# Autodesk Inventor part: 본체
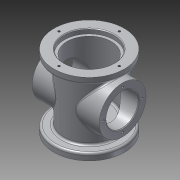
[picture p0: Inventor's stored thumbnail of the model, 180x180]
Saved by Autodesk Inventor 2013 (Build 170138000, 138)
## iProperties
Created: 2018-02
Part Number: 본체
Material: 알루미늄 6061
Document SubType Name: Modeling
Designer: Administrator
Density: 2.71 g/cm^3
Mass: 771.854 g
Surface Area: 821.824 cm^2
Volume: 284.817 cm^3
Author: Administrator
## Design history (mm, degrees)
sketch "스케치1"
  geometry: C1 r 38 at (0, 0); 1 further point
  constraints: 1 centre point, 1 coincident
  dimensions: "d0" = 76 diameter of C1
extrude "돌출1" new body sketch "스케치1" stored distance "d2" = 88; taper "d3" = 0 deg
sketch "스케치2"
  geometry: C1 r 38 at (0, 0) reference; C2 r 52.5 at (0, 0)
  constraints: 1 centre point, 1 coincident
  dimensions: "d5" = 105 diameter of C2
extrude "돌출2" join sketch "스케치2" distance "d7" = 10; taper "d8" = 0 deg
hole "구멍1" diameter "d11" = 66; stored, may be unused: countersink angle "d15" = 90 deg, drill point angle "d17" = 0 deg; dims "d9" = 10, "d10" = 10, "d12" = 6, "d13" = 74, "d14" = 7, "d16" = 86
hole "구멍2" diameter "d20" = 10; stored, may be unused: countersink angle "d24" = 90 deg, drill point angle "d26" = 0 deg; dims "d18" = 10, "d19" = 10, "d21" = 6, "d22" = 68, "d23" = 16, "d25" = 22
node "작업 평면1"
sketch "스케치3"
  geometry: C1 r 35 at (0, 0); 1 further point
  constraints: 1 centre point, 1 coincident
  dimensions: "d29" = 70 diameter of C1
extrude "돌출3" join sketch "스케치3" stored distance "d31" = 10; taper "d32" = 0 deg
hole "구멍3" diameter "d35" = 48; stored, may be unused: countersink angle "d39" = 90 deg, drill point angle "d41" = 0 deg; dims "d33" = 10, "d34" = 10, "d36" = 6, "d37" = 68, "d38" = 16, "d40" = 22
sketch "스케치4"
  geometry: C1 r 24 at (0, 0) reference; 1 further point
  constraints: 1 vertical alignment
  dimensions: "d42" = 29 distance of C1.centre point (0, 29)
hole "구멍4" sketch "스케치4" at (0, 29) diameter "d43" = 3.242; stored, may be unused: countersink angle "d47" = 90 deg, drill point angle "d49" = 118 deg; dims "d44" = 4, "d45" = 68, "d46" = 16, "d48" = 6
sketch "스케치5"
  geometry: C1 r 37 at (0, 0) reference; 1 further point
  constraints: 1 vertical alignment
  dimensions: "d53" = 45 distance of C1.centre point (0, 45)
hole "구멍5" sketch "스케치5" at (0, 45) diameter "d54" = 3.242; stored, may be unused: countersink angle "d58" = 90 deg, drill point angle "d60" = 118 deg; dims "d55" = 4, "d56" = 68, "d57" = 16, "d59" = 6
node "작업 평면2"
sketch "스케치6"
  geometry: L1 (-7, 13)-(-7, -13); L2 (7, 13)-(7, -13); A1 r 7 centre (0, 13) between (7, 13) and (-7, 13); A2 r 7 centre (0, -13) between (-7, -13) and (7, -13); 2 further points
  constraints: 4 end point, 4 point on circle, 4 tangent, 2 centre point, 2 vertical alignment, 1 equal radius, 1 horizontal alignment, 1 midpoint
  dimensions: "d65" = 14 diameter of A1; "d69" = 40 dimension on A2 A1
extrude "돌출4" join sketch "스케치6" stored distance "d70" = 10; taper "d71" = 15 deg
hole "구멍6" diameter "d74" = 4.134; stored, may be unused: countersink angle "d78" = 90 deg, drill point angle "d80" = 118 deg; dims "d72" = 10, "d73" = 10, "d75" = 6, "d76" = 68, "d77" = 16, "d79" = 8
hole "구멍7" diameter "d83" = 4.134; stored, may be unused: countersink angle "d87" = 90 deg, drill point angle "d89" = 118 deg; dims "d81" = 10, "d82" = 10, "d84" = 6, "d85" = 68, "d86" = 16, "d88" = 8
fillet "모깎기1" dims "d90" = 3
fillet "모깎기2" dims "d91" = 3
fillet "모깎기3" dims "d92" = 3
fillet "모깎기4" dims "d93" = 3
fillet "모깎기5" dims "d94" = 3
chamfer "모따기1" distance "d95" = 1; stored, may be unused: second distance "d96" = 2, angle "d97" = 45 deg
sketch "스케치7"
  geometry: C1 r 49.5 at (0, 0) reference; C2 r 43 at (0, 0)
  constraints: 1 centre point, 1 coincident, 1 other
  dimensions: "d101" = 86 diameter of C2
feature "엠보싱1" sketch "스케치7" dims "d103" = 0.5, "d104" = 0
chamfer "모따기2" distance "d105" = 1; stored, may be unused: second distance "d106" = 2, angle "d107" = 45 deg
node "솔리드1"
mirror "대칭1"
pattern_circular "원형 패턴1" dims angle "d51" = 360 deg
mirror "대칭2"
pattern_circular "원형 패턴2" dims angle "d62" = 360 deg
other parameters: "d64" = 55
